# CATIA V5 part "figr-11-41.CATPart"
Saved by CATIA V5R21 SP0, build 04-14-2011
Part number: Part1
Bounding box of the stored display mesh (mm): x -59 to 59, y -60 to 60, z 0 to 39.8
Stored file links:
  D:\CATIA V5R21 E-RESOURCES\CATIA-V5R21\catia-v5r21-prt\c11-catia-v5r21-prt\c11-catia-v5r21-figr-11-41.CATPart
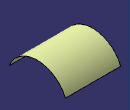
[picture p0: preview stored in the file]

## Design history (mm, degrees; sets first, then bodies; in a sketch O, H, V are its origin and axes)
Set1
  Extrude1: Element1 Sketch1, Lim1 59, Lim2 59, Direction yz-plane
Body1 (main body)
  Sketch1 on yz-plane, origin (0, 0, 0), H (0, 1, 0), V (0, 0, 1)
    arc A1 centre (0, -25) radius 65 from (-60, 0) to (60, 0) cw
    point P2 (-60, 0)
    point P3 (60, 0)
    coincidence: P2 H, P3 H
